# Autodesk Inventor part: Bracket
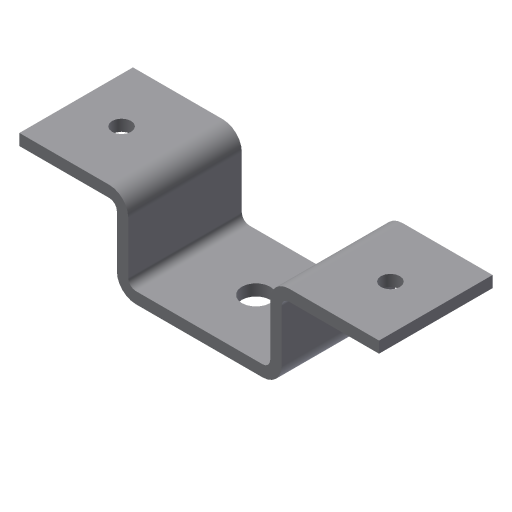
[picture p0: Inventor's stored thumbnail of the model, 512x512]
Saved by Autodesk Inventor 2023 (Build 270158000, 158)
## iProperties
Part Number: Bracket
Document SubType Name: Modeling
Created: 2003-01
Designer: Owner
Density: 1 g/cm^3
Material: Generic
Appearance: Default
Control State: 0
Master: False
Checked Out: False
Shininess: 64.0
Length Units: 11269
Angle Units: 11279
Time Units: 11290
Mass Units: 11283
Length Display Precision: 3
Angle Display Precision: 2
Compacted: True
Density: 0.0
Volumn: 0.0
Area: 0.0
PropertySet Name: Model Information
Author: Owner
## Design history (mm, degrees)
node "Sketch1"
sketch "Sketch2"
  geometry: L1 (487.39, 112.858)-(199.89, 112.858); L2 (199.89, 112.858)-(199.89, -95.142); L3 (199.89, -95.142)-(-175.11, -95.142); L4 (-175.11, -95.142)-(-175.11, 112.858); L5 (-175.11, 112.858)-(-462.61, 112.858); L6 (-462.61, 82.858)-(-205.11, 82.858); L7 (-205.11, 82.858)-(-205.11, -125.142); L8 (-205.11, -125.142)-(229.89, -125.142); L9 (229.89, -125.142)-(229.89, 82.858); L10 (229.89, 82.858)-(487.39, 82.858); L11 (487.39, 112.858)-(487.39, 82.858); L12 (-462.61, 112.858)-(-462.61, 82.858)
  constraints: 24 end point, 5 parallel, 3 perpendicular, 2 collinear, 2 equal length, 1 horizontal, 4 other
  dimensions: "d0" = 375 distance between parallel lines of L4 L2; "d1" = 950 distance of L5.end L1.start; "d2" = 30 distance between parallel lines of L1 L10; "d3" = 238 distance between parallel lines of L5 L8
extrude "Extrusion1" new body sketch "Sketch2" stored distance "d4" = 300; taper "d5" = 0 deg
fillet "Fillet1" dims "d6" = 20
fillet "Fillet2" dims "d7" = 50
sketch "Sketch3"
  geometry: L1 (237.5, 300)-(0, 300) reference; L2 (0, 300)-(0, 0) reference; 1 further point
  dimensions: "d8" = 120 distance from line of L2 point (120, 150); "d9" = 150 distance from line of L1 point (120, 150)
hole "Hole1" sketch "Sketch3" at (120, 150) diameter "d10" = 50; stored, may be unused: countersink angle "d14" = 82 deg, drill point angle "d16" = 118 deg; dims "d11" = 6, "d12" = 4, "d13" = 2, "d15" = 8
pattern_linear "Rectangular Pattern1" dims "d19" = 710
sketch "Sketch4"
  geometry: L1 (0, -300)-(335, -300) reference; 1 further point
  dimensions: "d20" = 150 distance from line of L1 point (167.5, -150)
hole "Hole2" sketch "Sketch4" at (167.5, -150) diameter "d21" = 75; stored, may be unused: countersink angle "d25" = 82 deg, drill point angle "d27" = 118 deg; dims "d22" = 6, "d23" = 4, "d24" = 2, "d26" = 8
body "Solid1"
